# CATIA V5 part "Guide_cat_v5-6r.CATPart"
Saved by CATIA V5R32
Part number: Guide
Bounding box of the stored display mesh (mm): x -5 to 5, y -5 to 5, z -25 to 25
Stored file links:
  D:\PROJECTS\Project 2022\CATIA V5 6R 2022\Resources\Tutorial Files\c16_catia_v5_6r2022_tut\Cam Follower mechanism\Guide_cat_v5-6r.CATPart
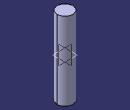
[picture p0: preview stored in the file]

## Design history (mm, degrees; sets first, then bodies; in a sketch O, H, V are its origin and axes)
Body1 (main body)
  Sketch1 on xy-plane, origin (0, 0, 0), H (1, 0, 0), V (0, 1, 0)
    circle A1 centre (0, 0) radius 5
    radius A1 = 5
  Pad1: profile Sketch1, direction (0, 0, 1), length 25, mirrored extent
